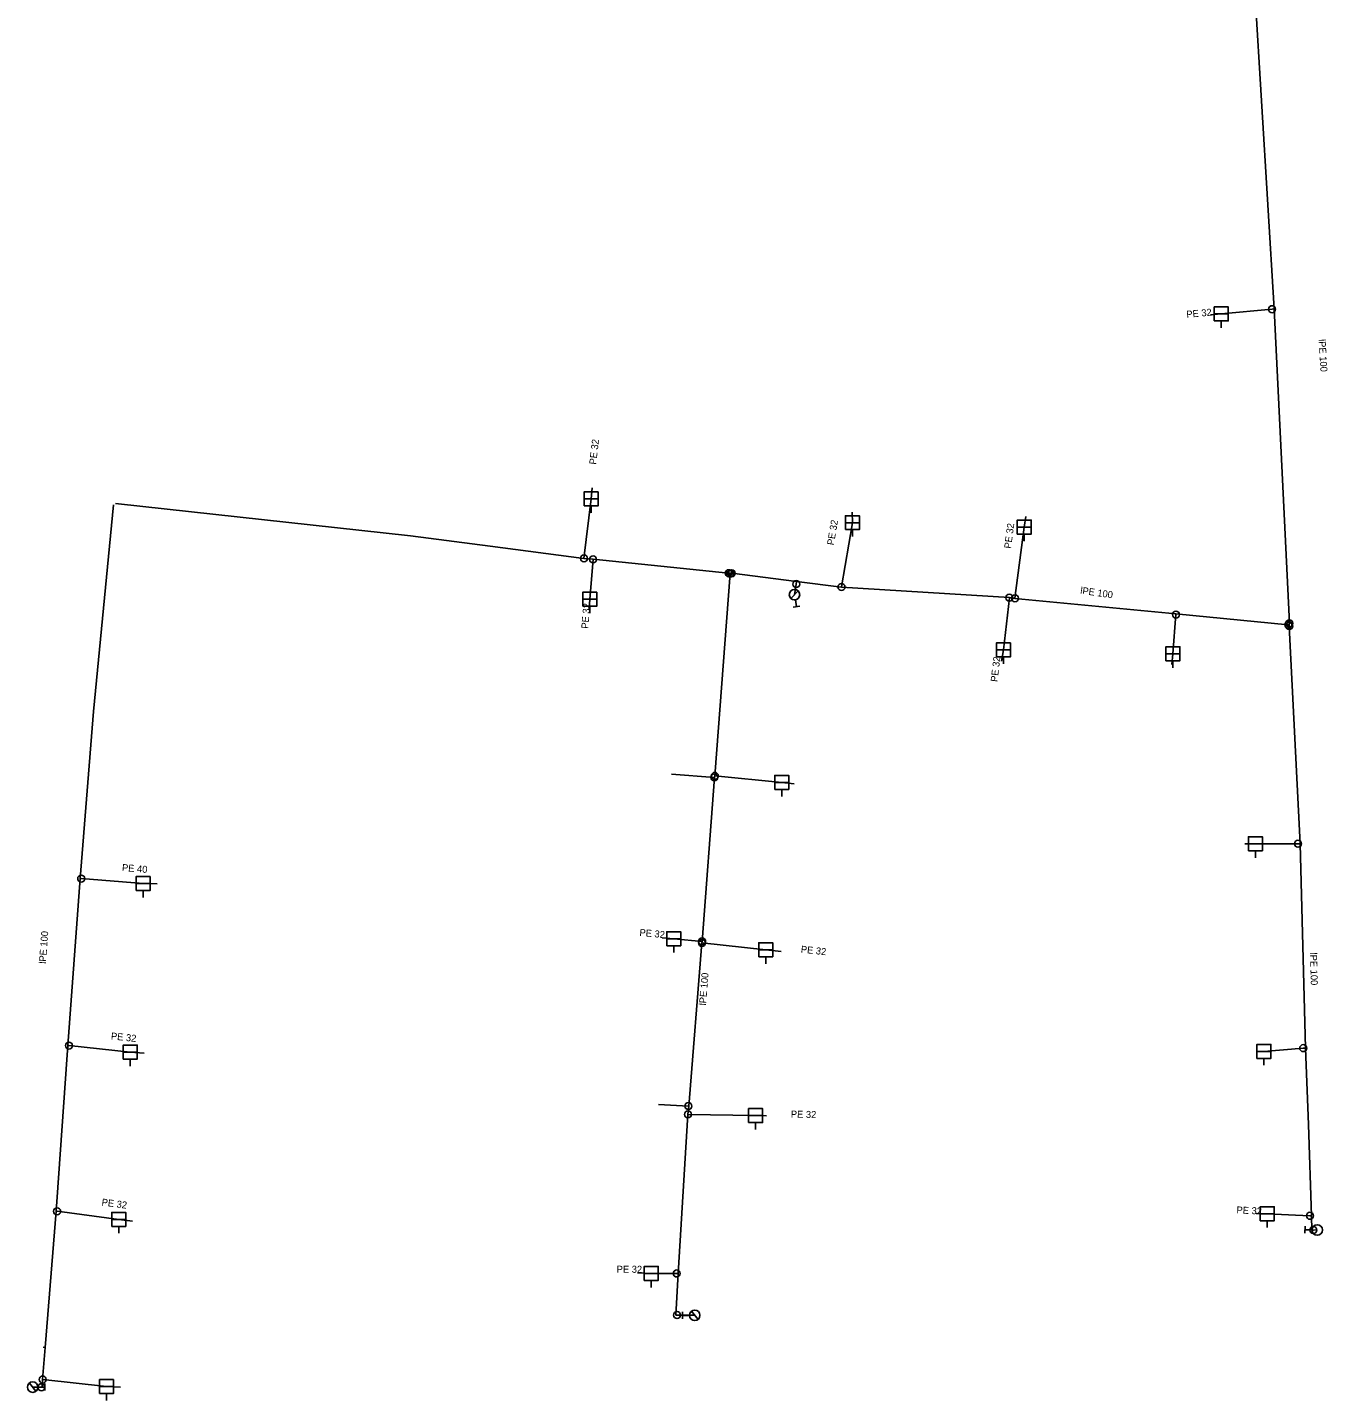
# Model space of a CAD drawing. Extents: x -725126 to -724740, y -1049524 to -1048684.
# Drawn here: x -725083.9 to -724897.7, y -1049524.1 to -1049327.5 of the extents above; entities that cross this region are included whole.
import ezdxf

# ---------------------------------------------------------------- set-up
doc = ezdxf.new("R2010")
doc.units = 0
doc.layers.add('Level 0', color=7, linetype='Continuous')

msp = doc.modelspace()

# ---------------------------------------------------------------- linework, layer by layer
at = {"layer": 'Level 0'}
for p, q in [((-724905.3, -1049367.83), (-724908.57, -1049314.24)), ((-724912.88, -1049368.53), (-724905.61, -1049367.86)), ((-724905.61, -1049367.86), (-724905.3, -1049367.83)), ((-724903.13, -1049412.83), (-724905.3, -1049367.83)), ((-724914.45, -1049368.66), (-724912.88, -1049368.53)), ((-724912.88, -1049370.53), (-724912.88, -1049369.53)), ((-725002.98, -1049393.44), (-725003.15, -1049395.01)), ((-725071.53, -1049395.87), (-725074.4, -1049425.46)), ((-725071.25, -1049395.66), (-725029.02, -1049400.32)), ((-725003.15, -1049395.01), (-725004.16, -1049403.54)), ((-725003.15, -1049397.01), (-725003.15, -1049396.01)), ((-724965.76, -1049396.92), (-724965.72, -1049398.42)), ((-724941.1, -1049399.05), (-724940.88, -1049397.55)), ((-724965.72, -1049398.42), (-724967.28, -1049407.63)), ((-724965.72, -1049400.42), (-724965.72, -1049399.42)), ((-724942.43, -1049409.24), (-724941.1, -1049399.05)), ((-725029.02, -1049400.32), (-725017.61, -1049401.8)), ((-725017.61, -1049401.8), (-725004.17, -1049403.56)), ((-724941.1, -1049401.05), (-724941.1, -1049400.05)), ((-725004.16, -1049403.54), (-725004.17, -1049403.56)), ((-725004.17, -1049403.56), (-725002.83, -1049403.63)), ((-725003.34, -1049409.39), (-725002.86, -1049403.68)), ((-725002.86, -1049403.68), (-725002.83, -1049403.63)), ((-725002.83, -1049403.63), (-724983.45, -1049405.65)), ((-724983.22, -1049405.72), (-724985.44, -1049434.66)), ((-724983.45, -1049405.65), (-724983.22, -1049405.67)), ((-724983.22, -1049405.67), (-724983, -1049405.66)), ((-724983.22, -1049405.67), (-724983.22, -1049405.72)), ((-724983, -1049405.66), (-724973.7, -1049406.84)), ((-724973.76, -1049407.21), (-724974.01, -1049408.73)), ((-724973.7, -1049406.84), (-724973.76, -1049407.21)), ((-724973.7, -1049406.84), (-724967.28, -1049407.65)), ((-724967.28, -1049407.63), (-724967.28, -1049407.65)), ((-724967.28, -1049407.65), (-724943.24, -1049409.14)), ((-725003.41, -1049410.86), (-725003.34, -1049409.39)), ((-724973.5, -1049408.18), (-724974.52, -1049409.28)), ((-724973.89, -1049409.47), (-724973.73, -1049410.46)), ((-724944.09, -1049416.64), (-724943.24, -1049409.16)), ((-724943.24, -1049409.16), (-724943.24, -1049409.14)), ((-724943.24, -1049409.14), (-724942.43, -1049409.26)), ((-724942.43, -1049409.26), (-724942.43, -1049409.24)), ((-724942.43, -1049409.26), (-724919.38, -1049411.48)), ((-725003.34, -1049411.39), (-725003.34, -1049410.39)), ((-724973.23, -1049410.38), (-724974.22, -1049410.54)), ((-724919.81, -1049417.18), (-724919.38, -1049411.58)), ((-724919.38, -1049411.58), (-724919.38, -1049411.48)), ((-724919.38, -1049411.48), (-724903.29, -1049413.03)), ((-724903.29, -1049413.03), (-724903.15, -1049413.04)), ((-724903.15, -1049413.04), (-724903.13, -1049412.83)), ((-724903.15, -1049413.04), (-724903.15, -1049413.22)), ((-724903.15, -1049413.22), (-724901.6, -1049444.38)), ((-724944.36, -1049418.25), (-724944.09, -1049416.64)), ((-724919.97, -1049418.72), (-724919.81, -1049417.18)), ((-724944.09, -1049418.64), (-724944.09, -1049417.64)), ((-724919.81, -1049419.18), (-724919.81, -1049418.18)), ((-725074.4, -1049425.46), (-725076.3, -1049449.36)), ((-724991.62, -1049434.44), (-724985.48, -1049434.88)), ((-724985.45, -1049434.89), (-724987.23, -1049458.37)), ((-724985.48, -1049434.88), (-724985.45, -1049434.89)), ((-724985.44, -1049434.66), (-724985.45, -1049434.89)), ((-724985.42, -1049434.66), (-724985.44, -1049434.66)), ((-724975.83, -1049435.61), (-724985.42, -1049434.66)), ((-724974.07, -1049435.79), (-724975.83, -1049435.61)), ((-724975.83, -1049437.61), (-724975.83, -1049436.61)), ((-724909.51, -1049444.39), (-724907.99, -1049444.38)), ((-724907.99, -1049444.38), (-724901.91, -1049444.38)), ((-724901.91, -1049444.38), (-724901.6, -1049444.38)), ((-724901.6, -1049444.38), (-724900.82, -1049473.64)), ((-724907.99, -1049446.38), (-724907.99, -1049445.38)), ((-725076.3, -1049449.36), (-725078.07, -1049473.27)), ((-725076.17, -1049449.37), (-725076.3, -1049449.36)), ((-725076.17, -1049449.37), (-725076.3, -1049449.36)), ((-725067.31, -1049450.09), (-725076.17, -1049449.37)), ((-725067.31, -1049450.09), (-725076.17, -1049449.37)), ((-725065.29, -1049450.14), (-725067.31, -1049450.09)), ((-725065.29, -1049450.14), (-725067.31, -1049450.09)), ((-725067.31, -1049452.09), (-725067.31, -1049451.09)), ((-724992.95, -1049457.88), (-724991.31, -1049457.98)), ((-724991.31, -1049457.98), (-724987.24, -1049458.37)), ((-724987.28, -1049458.59), (-724989.16, -1049481.95)), ((-724987.23, -1049458.37), (-724987.28, -1049458.59)), ((-724987.27, -1049458.59), (-724987.28, -1049458.59)), ((-724978.12, -1049459.56), (-724987.27, -1049458.59)), ((-724987.24, -1049458.37), (-724987.23, -1049458.37)), ((-724991.31, -1049459.98), (-724991.31, -1049458.98)), ((-724975.9, -1049459.8), (-724978.12, -1049459.56)), ((-724978.12, -1049461.56), (-724978.12, -1049460.56)), ((-725078.07, -1049473.27), (-725079.76, -1049496.99)), ((-725077.93, -1049473.29), (-725078.07, -1049473.27)), ((-725077.93, -1049473.29), (-725078.07, -1049473.27)), ((-725069.15, -1049474.21), (-725077.93, -1049473.29)), ((-725069.15, -1049474.21), (-725077.93, -1049473.29)), ((-725067.13, -1049474.38), (-725069.15, -1049474.21)), ((-725067.13, -1049474.38), (-725069.15, -1049474.21)), ((-724906.97, -1049474.12), (-724906.78, -1049474.11)), ((-724906.78, -1049474.11), (-724901.15, -1049473.65)), ((-724901.15, -1049473.65), (-724900.82, -1049473.64)), ((-724900.82, -1049473.64), (-724900.4, -1049484.57)), ((-725069.15, -1049476.21), (-725069.15, -1049475.21)), ((-724906.78, -1049476.11), (-724906.78, -1049475.11)), ((-724993.47, -1049481.7), (-724989.2, -1049481.94)), ((-724989.16, -1049481.95), (-724989.31, -1049483.13)), ((-724989.2, -1049481.94), (-724989.16, -1049481.95)), ((-724989.31, -1049483.13), (-724990.65, -1049505.91)), ((-724989.28, -1049483.13), (-724989.31, -1049483.13)), ((-724979.59, -1049483.3), (-724989.28, -1049483.13)), ((-724978.02, -1049483.36), (-724979.59, -1049483.3)), ((-724979.59, -1049485.3), (-724979.59, -1049484.3)), ((-724900.4, -1049484.57), (-724899.98, -1049497.65)), ((-725079.76, -1049496.99), (-725081.34, -1049516.51)), ((-725079.62, -1049497.01), (-725079.76, -1049496.99)), ((-725079.62, -1049497.01), (-725079.76, -1049496.99)), ((-725070.79, -1049498.16), (-725079.62, -1049497.01)), ((-725070.79, -1049498.16), (-725079.62, -1049497.01)), ((-725068.81, -1049498.42), (-725070.79, -1049498.16)), ((-725068.81, -1049498.42), (-725070.79, -1049498.16)), ((-724907.89, -1049497.31), (-724906.31, -1049497.35)), ((-724906.31, -1049497.35), (-724900.19, -1049497.65)), ((-724900.19, -1049497.65), (-724899.98, -1049497.65)), ((-724899.98, -1049497.65), (-724899.92, -1049499.7)), ((-725070.79, -1049500.16), (-725070.79, -1049499.16)), ((-724906.31, -1049499.35), (-724906.31, -1049498.35)), ((-724900.91, -1049500.15), (-724900.89, -1049499.15)), ((-724899.9, -1049499.67), (-724900.9, -1049499.65)), ((-724899.92, -1049499.7), (-724899.7, -1049499.69)), ((-724899.7, -1049499.69), (-724899.15, -1049499.68)), ((-724996.51, -1049505.81), (-724994.52, -1049505.9)), ((-724994.52, -1049505.9), (-724990.87, -1049505.91)), ((-724990.65, -1049505.91), (-724990.99, -1049511.88)), ((-724990.87, -1049505.91), (-724990.65, -1049505.91)), ((-724994.52, -1049507.9), (-724994.52, -1049506.9)), ((-724990.99, -1049511.88), (-724990.83, -1049511.87)), ((-724990.83, -1049511.87), (-724988.3, -1049511.9)), ((-724990.04, -1049512.42), (-724990.06, -1049511.42)), ((-724989.05, -1049511.91), (-724990.05, -1049511.92)), ((-724987.83, -1049512.48), (-724988.77, -1049511.31)), ((-725081.34, -1049516.51), (-725081.71, -1049521.08)), ((-725081.34, -1049516.51), (-725081.63, -1049516.48)), ((-725083.59, -1049521.6), (-725082.65, -1049522.77)), ((-725081.71, -1049521.08), (-725081.78, -1049522.2)), ((-725081.69, -1049521.09), (-725081.71, -1049521.08)), ((-725081.69, -1049521.09), (-725081.71, -1049521.08)), ((-725072.55, -1049522.1), (-725081.69, -1049521.09)), ((-725072.55, -1049522.1), (-725081.69, -1049521.09)), ((-725081.37, -1049521.67), (-725081.37, -1049522.67)), ((-725081.87, -1049522.19), (-725083.12, -1049522.18)), ((-725082.37, -1049522.17), (-725081.37, -1049522.17)), ((-725081.78, -1049522.2), (-725081.87, -1049522.19)), ((-725070.55, -1049522.17), (-725072.55, -1049522.1)), ((-725070.55, -1049522.17), (-725072.55, -1049522.1)), ((-725072.55, -1049524.1), (-725072.55, -1049523.1))]:
    msp.add_line(p, q, dxfattribs=at)
for points in [[(-724913.88, -1049368.53), (-724913.88, -1049367.53), (-724911.88, -1049367.53), (-724911.88, -1049368.53)], [(-725004.15, -1049395.01), (-725004.15, -1049394.01), (-725002.15, -1049394.01), (-725002.15, -1049395.01)], [(-724966.72, -1049398.42), (-724966.72, -1049397.42), (-724964.72, -1049397.42), (-724964.72, -1049398.42)], [(-724942.1, -1049399.05), (-724942.1, -1049398.05), (-724940.1, -1049398.05), (-724940.1, -1049399.05)], [(-725004.34, -1049409.39), (-725004.34, -1049408.39), (-725002.34, -1049408.39), (-725002.34, -1049409.39)], [(-724945.09, -1049416.64), (-724945.09, -1049415.64), (-724943.09, -1049415.64), (-724943.09, -1049416.64)], [(-724920.81, -1049417.18), (-724920.81, -1049416.18), (-724918.81, -1049416.18), (-724918.81, -1049417.18)], [(-724976.83, -1049435.61), (-724976.83, -1049434.61), (-724974.83, -1049434.61), (-724974.83, -1049435.61)], [(-724908.99, -1049444.38), (-724908.99, -1049443.38), (-724906.99, -1049443.38), (-724906.99, -1049444.38)], [(-725068.31, -1049450.09), (-725068.31, -1049449.09), (-725066.31, -1049449.09), (-725066.31, -1049450.09)], [(-724992.31, -1049457.98), (-724992.31, -1049456.98), (-724990.31, -1049456.98), (-724990.31, -1049457.98)], [(-724979.12, -1049459.56), (-724979.12, -1049458.56), (-724977.12, -1049458.56), (-724977.12, -1049459.56)], [(-725070.15, -1049474.21), (-725070.15, -1049473.21), (-725068.15, -1049473.21), (-725068.15, -1049474.21)], [(-724907.78, -1049474.11), (-724907.78, -1049473.11), (-724905.78, -1049473.11), (-724905.78, -1049474.11)], [(-724980.59, -1049483.3), (-724980.59, -1049482.3), (-724978.59, -1049482.3), (-724978.59, -1049483.3)], [(-725071.79, -1049498.16), (-725071.79, -1049497.16), (-725069.79, -1049497.16), (-725069.79, -1049498.16)], [(-724907.31, -1049497.35), (-724907.31, -1049496.35), (-724905.31, -1049496.35), (-724905.31, -1049497.35)], [(-724995.52, -1049505.9), (-724995.52, -1049504.9), (-724993.52, -1049504.9), (-724993.52, -1049505.9)], [(-725073.55, -1049522.1), (-725073.55, -1049521.1), (-725071.55, -1049521.1), (-725071.55, -1049522.1)]]:
    msp.add_lwpolyline(points, dxfattribs=at)
for points in [[(-724913.88, -1049369.53), (-724911.88, -1049369.53), (-724911.88, -1049368.53), (-724913.88, -1049368.53)], [(-725004.15, -1049396.01), (-725002.15, -1049396.01), (-725002.15, -1049395.01), (-725004.15, -1049395.01)], [(-724966.72, -1049399.42), (-724964.72, -1049399.42), (-724964.72, -1049398.42), (-724966.72, -1049398.42)], [(-724942.1, -1049400.05), (-724940.1, -1049400.05), (-724940.1, -1049399.05), (-724942.1, -1049399.05)], [(-725004.34, -1049410.39), (-725002.34, -1049410.39), (-725002.34, -1049409.39), (-725004.34, -1049409.39)], [(-724945.09, -1049417.64), (-724943.09, -1049417.64), (-724943.09, -1049416.64), (-724945.09, -1049416.64)], [(-724920.81, -1049418.18), (-724918.81, -1049418.18), (-724918.81, -1049417.18), (-724920.81, -1049417.18)], [(-724976.83, -1049436.61), (-724974.83, -1049436.61), (-724974.83, -1049435.61), (-724976.83, -1049435.61)], [(-724908.99, -1049445.38), (-724906.99, -1049445.38), (-724906.99, -1049444.38), (-724908.99, -1049444.38)], [(-725068.31, -1049451.09), (-725066.31, -1049451.09), (-725066.31, -1049450.09), (-725068.31, -1049450.09)], [(-724992.31, -1049458.98), (-724990.31, -1049458.98), (-724990.31, -1049457.98), (-724992.31, -1049457.98)], [(-724979.12, -1049460.56), (-724977.12, -1049460.56), (-724977.12, -1049459.56), (-724979.12, -1049459.56)], [(-725070.15, -1049475.21), (-725068.15, -1049475.21), (-725068.15, -1049474.21), (-725070.15, -1049474.21)], [(-724907.78, -1049475.11), (-724905.78, -1049475.11), (-724905.78, -1049474.11), (-724907.78, -1049474.11)], [(-724980.59, -1049484.3), (-724978.59, -1049484.3), (-724978.59, -1049483.3), (-724980.59, -1049483.3)], [(-725071.79, -1049499.16), (-725069.79, -1049499.16), (-725069.79, -1049498.16), (-725071.79, -1049498.16)], [(-724907.31, -1049498.35), (-724905.31, -1049498.35), (-724905.31, -1049497.35), (-724907.31, -1049497.35)], [(-724995.52, -1049506.9), (-724993.52, -1049506.9), (-724993.52, -1049505.9), (-724995.52, -1049505.9)], [(-725073.55, -1049523.1), (-725071.55, -1049523.1), (-725071.55, -1049522.1), (-725073.55, -1049522.1)]]:
    msp.add_lwpolyline(points, close=True, dxfattribs=at)
for centre, radius in [((-724905.61, -1049367.86), 0.5), ((-725004.16, -1049403.54), 0.5), ((-725002.86, -1049403.68), 0.5), ((-724983.45, -1049405.65), 0.5), ((-724983.22, -1049405.72), 0.5), ((-724983, -1049405.66), 0.5), ((-724973.76, -1049407.21), 0.5), ((-724967.28, -1049407.63), 0.5), ((-724974.01, -1049408.73), 0.75), ((-724943.24, -1049409.16), 0.5), ((-724942.43, -1049409.24), 0.5), ((-724919.38, -1049411.58), 0.5), ((-724903.29, -1049413.03), 0.5), ((-724903.15, -1049413.22), 0.5), ((-724903.13, -1049412.83), 0.5), ((-724985.48, -1049434.88), 0.5), ((-724985.42, -1049434.66), 0.5), ((-724901.91, -1049444.38), 0.5), ((-725076.17, -1049449.37), 0.5), ((-724987.27, -1049458.59), 0.5), ((-724987.24, -1049458.37), 0.5), ((-725077.93, -1049473.29), 0.5), ((-724901.15, -1049473.65), 0.5), ((-724989.2, -1049481.94), 0.5), ((-724989.28, -1049483.13), 0.5), ((-725079.62, -1049497.01), 0.5), ((-724900.19, -1049497.65), 0.5), ((-724899.7, -1049499.69), 0.5), ((-724899.15, -1049499.68), 0.75), ((-724990.87, -1049505.91), 0.5), ((-724990.83, -1049511.87), 0.5), ((-724988.3, -1049511.9), 0.75), ((-725083.12, -1049522.18), 0.75), ((-725081.87, -1049522.19), 0.5), ((-725081.69, -1049521.09), 0.5)]:
    msp.add_circle(centre, radius, dxfattribs=at)

# ---------------------------------------------------------------- texts
for s, rotation, p in [('PE 32', 5.265, (-724917.84, -1049369.1)), ('lPE 100', 273.492, (-724898.95, -1049372.18)), ('PE 32', 83.247, (-725002.43, -1049390.14)), ('PE 32', 80.386, (-724968.38, -1049401.7)), ('PE 32', 82.564, (-724943, -1049402.18)), ('lPE 100', 351.573, (-724933.12, -1049408.58)), ('PE 32', 85.195, (-725003.56, -1049413.63)), ('PE 32', 83.517, (-724944.93, -1049421.26)), ('PE 40', 355.354, (-725070.36, -1049448.28)), ('lPE 100', 85.766, (-725081.23, -1049461.59)), ('PE 32', 354.526, (-724996.25, -1049457.56)), ('PE 32', 353.949, (-724973.14, -1049459.97)), ('lPE 100', 271.527, (-724900.18, -1049459.98)), ('lPE 100', 85.399, (-724986.69, -1049467.56)), ('PE 32', 354.018, (-725071.95, -1049472.39)), ('PE 32', 358.995, (-724974.54, -1049483.59)), ('PE 32', 352.58, (-725073.29, -1049496.17)), ('PE 32', 357.194, (-724910.72, -1049497.3)), ('PE 32', 359.843, (-724999.48, -1049505.8))]:
    msp.add_text(s, height=1, rotation=rotation, dxfattribs=at).set_placement(p)

doc.saveas('drawing.dxf')
